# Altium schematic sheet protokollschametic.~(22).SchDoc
size A4; PageSetup: Record=PageOptions|CenterHorizontal=True|CenterVertical=True|PrintScale=0.87|XCorrection=1.00|YCorrection=1.00|PrintKind=2|BorderSize=5000000|LeftOffset=0|BottomOffset=0|Orientation=2|PaperLength=1000|PaperWidth=1000|Scale=100|PaperSource=7|PrintQuality=-4|MediaType=1|DitherType=10|PaperKind=Letter|PrintScaleMode=1
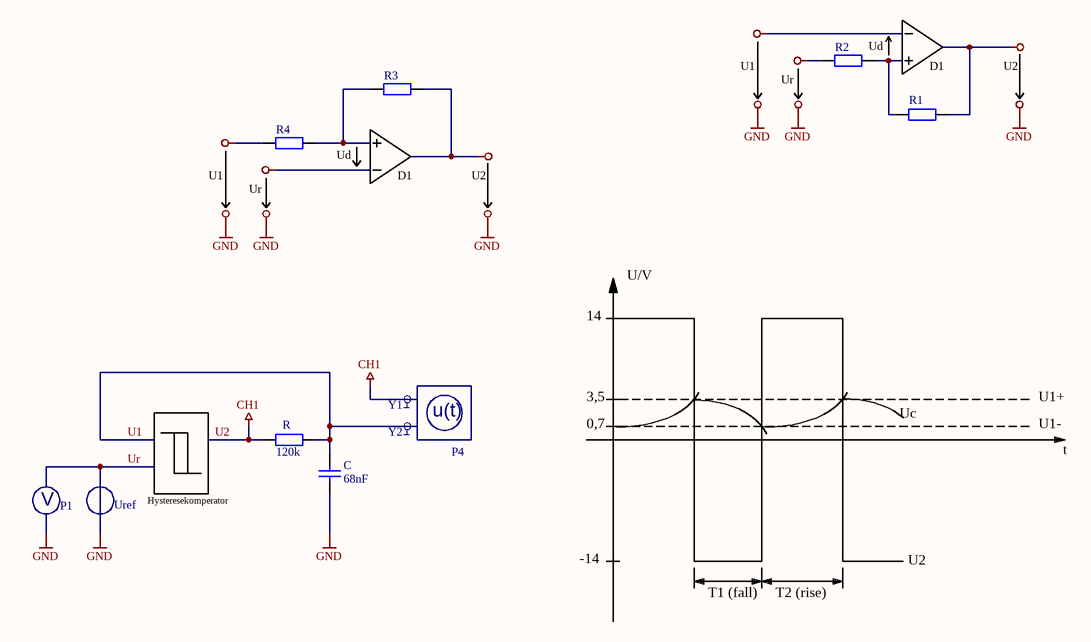
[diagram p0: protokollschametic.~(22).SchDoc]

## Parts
C  value 68nF  [RAD-0.3]  (hidden comment: Cap)
P1  Voltmeter1  (value not drawn)
P4  Oszilloskop2Kanal  (value not drawn)
R  value 120k  [AXIAL-0.4]  (hidden comment: Res2)
R1  Res2  [AXIAL-0.4]  (value not drawn)
R2  Res2  [AXIAL-0.4]  (value not drawn)
R3  Res2  [AXIAL-0.4]  (value not drawn)
R4  Res2  [AXIAL-0.4]  (value not drawn)
Uref  Spannungsquelle  (value not drawn)

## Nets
GND: C.1 P1.2 R1.2 R2.1 R3.2 R4.1 Uref.2
U2: P4.1 R.1  [also labelled CH1]
U1: C.2 P4.2 R.2
Ur: P1.1 Uref.1
NetR1_1: R1.1 R2.2
NetR3_1: R3.1 R4.2

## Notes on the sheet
- U1
- (near R2) Ur
- (near R2) Ud
- (near R1) D1
- U2
- (near R4) Ud
- (near R4) Ur
- D1
- U/V
- 14
- 0,7
- 3,5
- Uc
- U1+
- U1-
- Hysteresekomperator
- t
- -14
- T1 (fall)
- T2 (rise)

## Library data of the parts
C = Cap: Capacitor
R = Res2: Resistor
R1-R4 = Res2: Resistor; Value: 1K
